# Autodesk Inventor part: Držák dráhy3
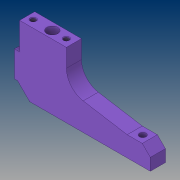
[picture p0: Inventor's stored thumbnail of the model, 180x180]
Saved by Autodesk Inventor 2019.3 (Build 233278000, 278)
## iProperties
Created: 2019-03
Part Number: Držák dráhy3
Material: Ocel, měkká, svařovaná
Document SubType Name: Modeling
Designer: B-hon
Density: 7.85 g/cm^3
Appearance: Fialová
Author: B-hon
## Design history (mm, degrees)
sketch "Náčrt1"
  geometry: L1 (0, 30)-(0, 0); L2 (0, 0)-(135, 0); L3 (30, -13.183)-(120, -13.183); L4 (0, 30)-(51.5, 30); L5 (51.5, 30)-(112, 20); L6 (112, 20)-(135, 20); L7 (135, 20)-(135, 0)
  constraints: 14 end point, 2 horizontal, 2 perpendicular, 1 parallel, 1 vertical
  dimensions: "d0" = 135 distance of L1.end L2.end; "d1" = 90 distance of L3.start L3.end; "d2" = 15 horizontal distance of L2.end L3.end; "d3" = 30 distance between parallel lines of L2 L4; "d4" = 20 distance between parallel lines of L2 L6; "d5" = 23 distance of L5.end L6.end; "d20" = 21.5 horizontal distance of L3.start L4.end
extrude "Vysunutí1" new body sketch "Náčrt1" distance "d8" = 15; taper "d9" = 0 deg
sketch "Náčrt4"
  geometry: L1 (0, 0)-(15, 0); L2 (15, 0)-(15, 12); L3 (15, 12)-(0, 12); L4 (0, 12)-(0, 0)
  constraints: 8 end point, 2 parallel, 1 horizontal, 1 perpendicular
  dimensions: "d24" = 15 distance of L3.end L2.end; "d25" = 12 distance of L2.end L1.end
extrude "Vysunutí3" cut sketch "Náčrt4" distance "d26" = 20; taper "d27" = 0 deg
chamfer "Zkosení2" distance "d32" = 12; stored, may be unused: second distance "d33" = 2, angle "d34" = 45 deg
chamfer "Zkosení3" distance "d35" = 8; stored, may be unused: second distance "d36" = 2, angle "d37" = 45 deg
sketch "Náčrt6"
  geometry: L1 (51.5, 0)-(51.5, -15) reference; L2 (0, 0)-(51.5, 0); L3 (51.5, 0)-(51.5, -15); L4 (51.5, -15)-(0, -15); L5 (0, -15)-(0, 0)
  constraints: 8 end point, 2 parallel, 1 horizontal, 1 perpendicular
extrude "Vysunutí4" join sketch "Náčrt6" distance "d38" = 35; taper "d39" = 0 deg
sketch "Náčrt2"
  geometry: L1 (0, 15)-(135, 15) reference; L2 (135, 0)-(135, 15) reference; 3 further points
  constraints: 1 horizontal alignment
  dimensions: "d10" = 7.5 distance from line of L1 point (30, 7.5); "d11" = 90 distance of point (120, 7.5) point (30, 7.5); "d12" = 15 distance from line of L2 point (120, 7.5)
hole "Díra1" sketch "Náčrt2" at (30, 7.5), (120, 7.5) diameter "d13" = 6.5; stored, may be unused: countersink angle "d17" = 90 deg, drill point angle "d19" = 118 deg; dims "d14" = 6, "d15" = 4, "d16" = 2, "d18" = 8
fillet "Zaoblení2" dims "d40" = 20
sketch "Náčrt7"
  geometry: L1 (51.5, 65)-(0, 65) reference; L2 (0, 65)-(5, 65); L3 (5, 65)-(5, 38); L4 (5, 38)-(0, 38); L5 (0, 38)-(0, 65); 1 further point
  constraints: 8 end point, 2 parallel, 1 horizontal, 1 perpendicular
  dimensions: "d41" = 5 distance of L3.end L4.end; "d42" = 27 distance of L2.end L3.end
extrude "Vysunutí5" cut sketch "Náčrt7" distance "d43" = 35; taper "d44" = 0 deg
sketch "Náčrt8"
  geometry: C1 r 3.25 at (30, -7.5) reference; 2 further points
  constraints: 1 coincident
hole "Díra2" sketch "Náčrt8" at (30, -7.5) diameter "d45" = 11; stored, may be unused: countersink angle "d49" = 90 deg, drill point angle "d51" = 0 deg; dims "d46" = 6, "d47" = 4, "d48" = 2, "d50" = 8
sketch "Náčrt9"
  geometry: L1 (51.5, 0)-(5, 0) reference; L2 (5, 0)-(5, -15) reference; L3 (51.5, -15)-(51.5, 0) reference; 3 further points
  constraints: 1 horizontal alignment
  dimensions: "d52" = 7.5 distance from line of L1 point (11, -7.5); "d53" = 6 distance from line of L2 point (11, -7.5); "d54" = 7.5 distance from line of L3 point (44, -7.5)
hole "Díra3" sketch "Náčrt9" at (11, -7.5), (44, -7.5) diameter "d55" = 4.917; stored, may be unused: countersink angle "d59" = 90 deg, drill point angle "d61" = 118 deg; dims "d56" = 12, "d57" = 6, "d58" = 2, "d60" = 17.1
node "Těleso1"
